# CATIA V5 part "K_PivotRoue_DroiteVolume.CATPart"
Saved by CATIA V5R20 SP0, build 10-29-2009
Part number: pivot_roue_droite_volume
Bounding box of the stored display mesh (mm): x -30 to 30, y -635 to -426.667, z -19.994 to 19.994
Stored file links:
  G:\Khaled_CFAO_2011\ST2M\ST2M_GR1\cdurantin\cdurantin\Khaled\CAD_ThinkMOTION\K_PivotRoue_DroiteVolume.CATPart
  C:\Documents and Settings\cdurantin\Bureau\cdurantin\caddy.CATProduct
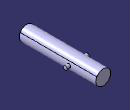
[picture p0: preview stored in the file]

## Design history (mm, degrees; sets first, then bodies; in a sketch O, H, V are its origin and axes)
Body1 (main body)
Body2
  Solid1: linked copy from another document
  Symmetry1: Reference zx-plane, ToTransfor Solid1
